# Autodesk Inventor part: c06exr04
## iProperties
Created: 2001-12
Part Number: c06exr04
Document SubType Name: Modeling
Control State: 0
Master: False
Checked Out: False
Shininess: 77.0
Length Units: 11269
Angle Units: 11279
Time Units: 11290
Mass Units: 11283
Length Display Precision: 3
Angle Display Precision: 2
Density: 0.0
Volumn: 0.0
Area: 0.0
PropertySet Name: Model Information
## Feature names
1. Extrusion1
2. Extrusion2
3. Extrusion3
4. Extrusion4
5. Extrusion5
6. Extrusion6
7. Hole1
8. Hole2
9. Hole3
